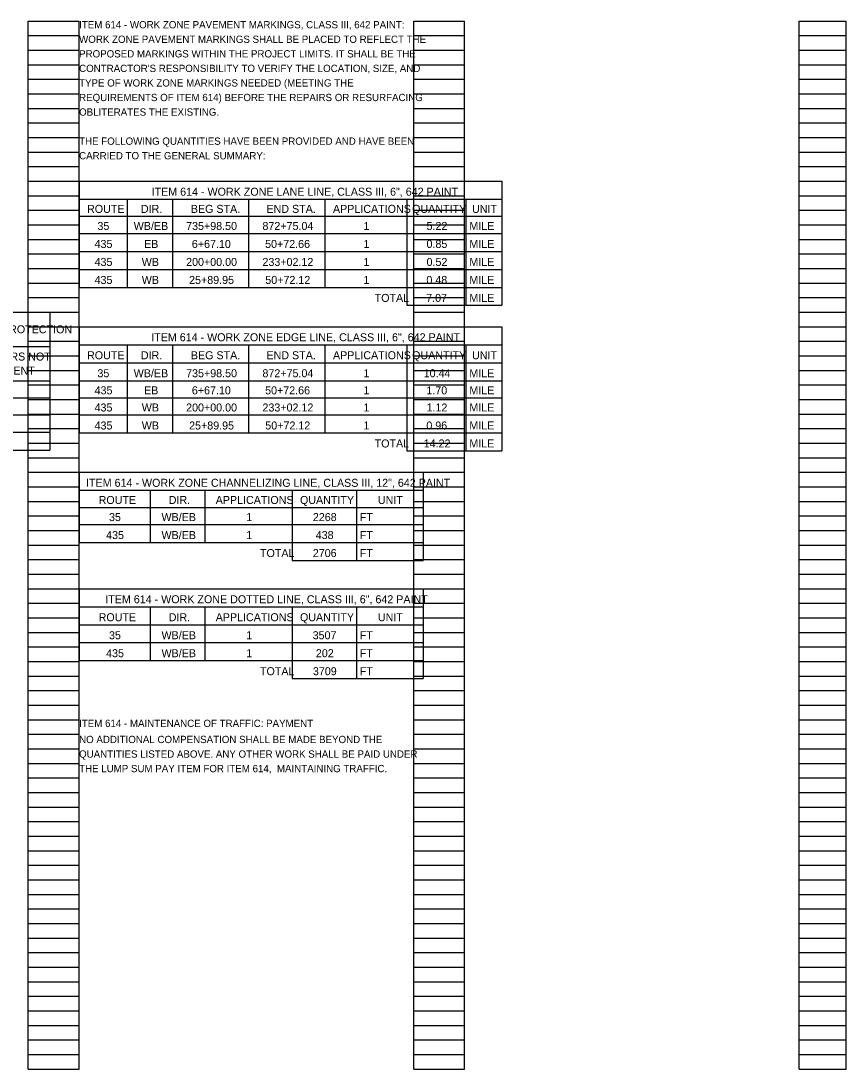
# Model space of a CAD drawing. Extents: x 51924.2 to 51956.2, y 31431.6 to 31530.7.
# Drawn here: x 51940.33 to 51956.21, y 31432.54 to 31452.7 of the extents above; entities that cross this region are included whole.
import ezdxf

# ---------------------------------------------------------------- set-up
doc = ezdxf.new("R2010")
doc.units = 0
doc.layers.add('SH_Data', color=7, linetype='Continuous')
doc.layers.add('SH_Text', color=7, linetype='Continuous')

msp = doc.modelspace()

# ---------------------------------------------------------------- linework, layer by layer
at = {"layer": 'SH_Data'}
for p, q in [((51940.468, 31432.54), (51940.468, 31452.7)), ((51940.468, 31452.7), (51941.448, 31452.7)), ((51941.448, 31432.54), (51941.448, 31452.7)), ((51947.888, 31432.54), (51947.888, 31452.7)), ((51947.888, 31452.7), (51948.868, 31452.7)), ((51948.868, 31432.54), (51948.868, 31452.7)), ((51955.308, 31432.54), (51955.308, 31452.7)), ((51955.308, 31452.7), (51956.208, 31452.7)), ((51956.208, 31432.54), (51956.208, 31452.7)), ((51940.468, 31452.42), (51941.448, 31452.42)), ((51947.888, 31452.42), (51948.868, 31452.42)), ((51955.308, 31452.42), (51956.208, 31452.42)), ((51940.468, 31452.14), (51941.448, 31452.14)), ((51947.888, 31452.14), (51948.868, 31452.14)), ((51955.308, 31452.14), (51956.208, 31452.14)), ((51940.468, 31451.86), (51941.448, 31451.86)), ((51947.888, 31451.86), (51948.868, 31451.86)), ((51955.308, 31451.86), (51956.208, 31451.86)), ((51940.468, 31451.58), (51941.448, 31451.58)), ((51947.888, 31451.58), (51948.868, 31451.58)), ((51955.308, 31451.58), (51956.208, 31451.58)), ((51940.468, 31451.3), (51941.448, 31451.3)), ((51947.888, 31451.3), (51948.868, 31451.3)), ((51955.308, 31451.3), (51956.208, 31451.3)), ((51940.468, 31451.02), (51941.448, 31451.02)), ((51947.888, 31451.02), (51948.868, 31451.02)), ((51955.308, 31451.02), (51956.208, 31451.02)), ((51940.468, 31450.74), (51941.448, 31450.74)), ((51947.888, 31450.74), (51948.868, 31450.74)), ((51955.308, 31450.74), (51956.208, 31450.74)), ((51940.468, 31450.46), (51941.448, 31450.46)), ((51947.888, 31450.46), (51948.868, 31450.46)), ((51955.308, 31450.46), (51956.208, 31450.46)), ((51940.468, 31450.18), (51941.448, 31450.18)), ((51947.888, 31450.18), (51948.868, 31450.18)), ((51955.308, 31450.18), (51956.208, 31450.18)), ((51940.468, 31449.9), (51941.448, 31449.9)), ((51947.888, 31449.9), (51948.868, 31449.9)), ((51955.308, 31449.9), (51956.208, 31449.9)), ((51940.468, 31449.62), (51941.448, 31449.62)), ((51947.888, 31449.62), (51948.868, 31449.62)), ((51955.308, 31449.62), (51956.208, 31449.62)), ((51940.468, 31449.34), (51941.448, 31449.34)), ((51947.888, 31449.34), (51948.868, 31449.34)), ((51955.308, 31449.34), (51956.208, 31449.34)), ((51940.468, 31449.06), (51941.448, 31449.06)), ((51947.888, 31449.06), (51948.868, 31449.06)), ((51955.308, 31449.06), (51956.208, 31449.06)), ((51940.468, 31448.78), (51941.448, 31448.78)), ((51947.888, 31448.78), (51948.868, 31448.78)), ((51955.308, 31448.78), (51956.208, 31448.78)), ((51940.468, 31448.5), (51941.448, 31448.5)), ((51947.888, 31448.5), (51948.868, 31448.5)), ((51955.308, 31448.5), (51956.208, 31448.5)), ((51940.468, 31448.22), (51941.448, 31448.22)), ((51947.888, 31448.22), (51948.868, 31448.22)), ((51955.308, 31448.22), (51956.208, 31448.22)), ((51940.468, 31447.94), (51941.448, 31447.94)), ((51947.888, 31447.94), (51948.868, 31447.94)), ((51955.308, 31447.94), (51956.208, 31447.94)), ((51940.468, 31447.66), (51941.448, 31447.66)), ((51947.888, 31447.66), (51948.868, 31447.66)), ((51955.308, 31447.66), (51956.208, 31447.66)), ((51940.468, 31447.38), (51941.448, 31447.38)), ((51947.888, 31447.38), (51948.868, 31447.38)), ((51955.308, 31447.38), (51956.208, 31447.38)), ((51940.468, 31447.1), (51941.448, 31447.1)), ((51947.888, 31447.1), (51948.868, 31447.1)), ((51955.308, 31447.1), (51956.208, 31447.1)), ((51940.468, 31446.82), (51941.448, 31446.82)), ((51947.888, 31446.82), (51948.868, 31446.82)), ((51955.308, 31446.82), (51956.208, 31446.82)), ((51940.468, 31446.54), (51941.448, 31446.54)), ((51947.888, 31446.54), (51948.868, 31446.54)), ((51955.308, 31446.54), (51956.208, 31446.54)), ((51940.468, 31446.26), (51941.448, 31446.26)), ((51947.888, 31446.26), (51948.868, 31446.26)), ((51955.308, 31446.26), (51956.208, 31446.26)), ((51940.468, 31445.98), (51941.448, 31445.98)), ((51947.888, 31445.98), (51948.868, 31445.98)), ((51955.308, 31445.98), (51956.208, 31445.98)), ((51940.468, 31445.7), (51941.448, 31445.7)), ((51947.888, 31445.7), (51948.868, 31445.7)), ((51955.308, 31445.7), (51956.208, 31445.7)), ((51940.468, 31445.42), (51941.448, 31445.42)), ((51947.888, 31445.42), (51948.868, 31445.42)), ((51955.308, 31445.42), (51956.208, 31445.42)), ((51940.468, 31445.14), (51941.448, 31445.14)), ((51947.888, 31445.14), (51948.868, 31445.14)), ((51955.308, 31445.14), (51956.208, 31445.14)), ((51940.468, 31444.86), (51941.448, 31444.86)), ((51947.888, 31444.86), (51948.868, 31444.86)), ((51955.308, 31444.86), (51956.208, 31444.86)), ((51940.468, 31444.58), (51941.448, 31444.58)), ((51947.888, 31444.58), (51948.868, 31444.58)), ((51955.308, 31444.58), (51956.208, 31444.58)), ((51940.468, 31444.3), (51941.448, 31444.3)), ((51947.888, 31444.3), (51948.868, 31444.3)), ((51955.308, 31444.3), (51956.208, 31444.3)), ((51940.468, 31444.02), (51941.448, 31444.02)), ((51947.888, 31444.02), (51948.868, 31444.02)), ((51955.308, 31444.02), (51956.208, 31444.02)), ((51940.468, 31443.74), (51941.448, 31443.74)), ((51947.888, 31443.74), (51948.868, 31443.74)), ((51955.308, 31443.74), (51956.208, 31443.74)), ((51940.468, 31443.46), (51941.448, 31443.46)), ((51947.888, 31443.46), (51948.868, 31443.46)), ((51955.308, 31443.46), (51956.208, 31443.46)), ((51940.468, 31443.18), (51941.448, 31443.18)), ((51947.888, 31443.18), (51948.868, 31443.18)), ((51955.308, 31443.18), (51956.208, 31443.18)), ((51940.468, 31442.9), (51941.448, 31442.9)), ((51947.888, 31442.9), (51948.868, 31442.9)), ((51955.308, 31442.9), (51956.208, 31442.9)), ((51940.468, 31442.62), (51941.448, 31442.62)), ((51947.888, 31442.62), (51948.868, 31442.62)), ((51955.308, 31442.62), (51956.208, 31442.62)), ((51940.468, 31442.34), (51941.448, 31442.34)), ((51947.888, 31442.34), (51948.868, 31442.34)), ((51955.308, 31442.34), (51956.208, 31442.34)), ((51940.468, 31442.06), (51941.448, 31442.06)), ((51947.888, 31442.06), (51948.868, 31442.06)), ((51955.308, 31442.06), (51956.208, 31442.06)), ((51940.468, 31441.78), (51941.448, 31441.78)), ((51947.888, 31441.78), (51948.868, 31441.78)), ((51955.308, 31441.78), (51956.208, 31441.78)), ((51940.468, 31441.5), (51941.448, 31441.5)), ((51947.888, 31441.5), (51948.868, 31441.5)), ((51955.308, 31441.5), (51956.208, 31441.5)), ((51940.468, 31441.22), (51941.448, 31441.22)), ((51947.888, 31441.22), (51948.868, 31441.22)), ((51955.308, 31441.22), (51956.208, 31441.22)), ((51940.468, 31440.94), (51941.448, 31440.94)), ((51947.888, 31440.94), (51948.868, 31440.94)), ((51955.308, 31440.94), (51956.208, 31440.94)), ((51940.468, 31440.66), (51941.448, 31440.66)), ((51947.888, 31440.66), (51948.868, 31440.66)), ((51955.308, 31440.66), (51956.208, 31440.66)), ((51940.468, 31440.38), (51941.448, 31440.38)), ((51947.888, 31440.38), (51948.868, 31440.38)), ((51955.308, 31440.38), (51956.208, 31440.38)), ((51940.468, 31440.1), (51941.448, 31440.1)), ((51947.888, 31440.1), (51948.868, 31440.1)), ((51955.308, 31440.1), (51956.208, 31440.1)), ((51940.468, 31439.82), (51941.448, 31439.82)), ((51947.888, 31439.82), (51948.868, 31439.82)), ((51955.308, 31439.82), (51956.208, 31439.82)), ((51940.468, 31439.54), (51941.448, 31439.54)), ((51947.888, 31439.54), (51948.868, 31439.54)), ((51955.308, 31439.54), (51956.208, 31439.54)), ((51940.468, 31439.26), (51941.448, 31439.26)), ((51947.888, 31439.26), (51948.868, 31439.26)), ((51955.308, 31439.26), (51956.208, 31439.26)), ((51940.468, 31438.98), (51941.448, 31438.98)), ((51947.888, 31438.98), (51948.868, 31438.98)), ((51955.308, 31438.98), (51956.208, 31438.98)), ((51940.468, 31438.7), (51941.448, 31438.7)), ((51947.888, 31438.7), (51948.868, 31438.7)), ((51955.308, 31438.7), (51956.208, 31438.7)), ((51940.468, 31438.42), (51941.448, 31438.42)), ((51947.888, 31438.42), (51948.868, 31438.42)), ((51955.308, 31438.42), (51956.208, 31438.42)), ((51940.468, 31438.14), (51941.448, 31438.14)), ((51947.888, 31438.14), (51948.868, 31438.14)), ((51955.308, 31438.14), (51956.208, 31438.14)), ((51940.468, 31437.86), (51941.448, 31437.86)), ((51947.888, 31437.86), (51948.868, 31437.86)), ((51955.308, 31437.86), (51956.208, 31437.86)), ((51940.468, 31437.58), (51941.448, 31437.58)), ((51947.888, 31437.58), (51948.868, 31437.58)), ((51955.308, 31437.58), (51956.208, 31437.58)), ((51940.468, 31437.3), (51941.448, 31437.3)), ((51947.888, 31437.3), (51948.868, 31437.3)), ((51955.308, 31437.3), (51956.208, 31437.3)), ((51940.468, 31437.02), (51941.448, 31437.02)), ((51947.888, 31437.02), (51948.868, 31437.02)), ((51955.308, 31437.02), (51956.208, 31437.02)), ((51940.468, 31436.74), (51941.448, 31436.74)), ((51947.888, 31436.74), (51948.868, 31436.74)), ((51955.308, 31436.74), (51956.208, 31436.74)), ((51940.468, 31436.46), (51941.448, 31436.46)), ((51947.888, 31436.46), (51948.868, 31436.46)), ((51955.308, 31436.46), (51956.208, 31436.46)), ((51940.468, 31436.18), (51941.448, 31436.18)), ((51947.888, 31436.18), (51948.868, 31436.18)), ((51955.308, 31436.18), (51956.208, 31436.18)), ((51940.468, 31435.9), (51941.448, 31435.9)), ((51947.888, 31435.9), (51948.868, 31435.9)), ((51955.308, 31435.9), (51956.208, 31435.9)), ((51940.468, 31435.62), (51941.448, 31435.62)), ((51947.888, 31435.62), (51948.868, 31435.62)), ((51955.308, 31435.62), (51956.208, 31435.62)), ((51940.468, 31435.34), (51941.448, 31435.34)), ((51947.888, 31435.34), (51948.868, 31435.34)), ((51955.308, 31435.34), (51956.208, 31435.34)), ((51940.468, 31435.06), (51941.448, 31435.06)), ((51947.888, 31435.06), (51948.868, 31435.06)), ((51955.308, 31435.06), (51956.208, 31435.06)), ((51940.468, 31434.78), (51941.448, 31434.78)), ((51947.888, 31434.78), (51948.868, 31434.78)), ((51955.308, 31434.78), (51956.208, 31434.78)), ((51940.468, 31434.5), (51941.448, 31434.5)), ((51947.888, 31434.5), (51948.868, 31434.5)), ((51955.308, 31434.5), (51956.208, 31434.5)), ((51940.468, 31434.22), (51941.448, 31434.22)), ((51947.888, 31434.22), (51948.868, 31434.22)), ((51955.308, 31434.22), (51956.208, 31434.22)), ((51940.468, 31433.94), (51941.448, 31433.94)), ((51947.888, 31433.94), (51948.868, 31433.94)), ((51955.308, 31433.94), (51956.208, 31433.94)), ((51940.468, 31433.66), (51941.448, 31433.66)), ((51947.888, 31433.66), (51948.868, 31433.66)), ((51955.308, 31433.66), (51956.208, 31433.66)), ((51940.468, 31433.38), (51941.448, 31433.38)), ((51947.888, 31433.38), (51948.868, 31433.38)), ((51955.308, 31433.38), (51956.208, 31433.38)), ((51940.468, 31433.1), (51941.448, 31433.1)), ((51947.888, 31433.1), (51948.868, 31433.1)), ((51955.308, 31433.1), (51956.208, 31433.1)), ((51940.468, 31432.82), (51941.448, 31432.82)), ((51947.888, 31432.82), (51948.868, 31432.82)), ((51955.308, 31432.82), (51956.208, 31432.82)), ((51940.468, 31432.54), (51941.448, 31432.54)), ((51947.888, 31432.54), (51948.868, 31432.54)), ((51955.308, 31432.54), (51956.208, 31432.54))]:
    msp.add_line(p, q, dxfattribs=at)
at = {"layer": 'SH_Text'}
for p, q in [((51941.448, 31449.62), (51949.585, 31449.62)), ((51941.448, 31449.62), (51941.448, 31447.577)), ((51949.585, 31449.62), (51949.585, 31447.232)), ((51941.448, 31449.274), (51949.585, 31449.274)), ((51942.371, 31449.274), (51942.371, 31447.577)), ((51943.244, 31449.274), (51943.244, 31447.577)), ((51944.71, 31449.274), (51944.71, 31447.577)), ((51946.176, 31449.274), (51946.176, 31447.577)), ((51947.757, 31449.274), (51947.757, 31447.577)), ((51948.893, 31449.274), (51948.893, 31447.232)), ((51941.448, 31448.944), (51949.585, 31448.944)), ((51941.448, 31448.615), (51949.585, 31448.615)), ((51941.448, 31448.269), (51949.585, 31448.269)), ((51941.448, 31447.923), (51949.585, 31447.923)), ((51941.448, 31447.577), (51949.585, 31447.577)), ((51947.757, 31447.577), (51947.757, 31447.232)), ((51947.757, 31447.232), (51949.585, 31447.232)), ((51933.048, 31447.1), (51940.888, 31447.1)), ((51940.888, 31447.1), (51940.888, 31444.448)), ((51941.448, 31446.82), (51949.585, 31446.82)), ((51941.448, 31446.82), (51941.448, 31444.777)), ((51949.585, 31446.82), (51949.585, 31444.432)), ((51933.048, 31446.441), (51940.888, 31446.441)), ((51941.448, 31446.474), (51949.585, 31446.474)), ((51942.371, 31446.474), (51942.371, 31444.777)), ((51943.244, 31446.474), (51943.244, 31444.777)), ((51944.71, 31446.474), (51944.71, 31444.777)), ((51946.176, 31446.474), (51946.176, 31444.777)), ((51947.757, 31446.474), (51947.757, 31444.777)), ((51948.893, 31446.474), (51948.893, 31444.432)), ((51941.448, 31446.128), (51949.585, 31446.128)), ((51933.048, 31445.782), (51940.888, 31445.782)), ((51941.448, 31445.782), (51949.585, 31445.782)), ((51933.048, 31445.453), (51940.888, 31445.453)), ((51941.448, 31445.453), (51949.585, 31445.453)), ((51933.048, 31445.123), (51940.888, 31445.123)), ((51941.448, 31445.123), (51949.585, 31445.123)), ((51933.048, 31444.794), (51940.888, 31444.794)), ((51941.448, 31444.777), (51949.585, 31444.777)), ((51947.757, 31444.777), (51947.757, 31444.432)), ((51933.048, 31444.448), (51940.888, 31444.448)), ((51947.757, 31444.432), (51949.585, 31444.432)), ((51941.448, 31444.02), (51948.07, 31444.02)), ((51941.448, 31444.02), (51941.448, 31442.669)), ((51948.07, 31444.02), (51948.07, 31442.323)), ((51941.448, 31443.674), (51948.07, 31443.674)), ((51942.816, 31443.674), (51942.816, 31442.669)), ((51943.87, 31443.674), (51943.87, 31442.669)), ((51945.55, 31443.674), (51945.55, 31442.669)), ((51946.785, 31443.674), (51946.785, 31442.323)), ((51941.448, 31443.344), (51948.07, 31443.344)), ((51941.448, 31443.015), (51948.07, 31443.015)), ((51941.448, 31442.669), (51948.07, 31442.669)), ((51945.55, 31442.669), (51945.55, 31442.323)), ((51945.55, 31442.323), (51948.07, 31442.323)), ((51941.448, 31441.78), (51948.07, 31441.78)), ((51941.448, 31441.78), (51941.448, 31440.396)), ((51948.07, 31441.78), (51948.07, 31440.05)), ((51941.448, 31441.434), (51948.07, 31441.434)), ((51942.816, 31441.434), (51942.816, 31440.396)), ((51943.87, 31441.434), (51943.87, 31440.396)), ((51945.55, 31441.434), (51945.55, 31440.396)), ((51946.785, 31441.434), (51946.785, 31440.05)), ((51941.448, 31441.088), (51948.07, 31441.088)), ((51941.448, 31440.742), (51948.07, 31440.742)), ((51941.448, 31440.396), (51948.07, 31440.396)), ((51945.55, 31440.396), (51945.55, 31440.05)), ((51945.55, 31440.05), (51948.07, 31440.05))]:
    msp.add_line(p, q, dxfattribs=at)

# ---------------------------------------------------------------- texts
for s, height, p in [('ITEM 614 - WORK ZONE PAVEMENT MARKINGS, CLASS III, 642 PAINT:', 0.14, (51941.448, 31452.56)), ('WORK ZONE PAVEMENT MARKINGS SHALL BE PLACED TO REFLECT THE ', 0.14, (51941.448, 31452.28)), ('PROPOSED MARKINGS WITHIN THE PROJECT LIMITS. IT SHALL BE THE ', 0.14, (51941.448, 31452)), ("CONTRACTOR'S RESPONSIBILITY TO VERIFY THE LOCATION, SIZE, AND ", 0.14, (51941.448, 31451.72)), ('TYPE OF WORK ZONE MARKINGS NEEDED (MEETING THE ', 0.14, (51941.448, 31451.44)), ('REQUIREMENTS OF ITEM 614) BEFORE THE REPAIRS OR RESURFACING ', 0.14, (51941.448, 31451.16)), ('OBLITERATES THE EXISTING.', 0.14, (51941.448, 31450.88)), ('THE FOLLOWING QUANTITIES HAVE BEEN PROVIDED AND HAVE BEEN ', 0.14, (51941.448, 31450.32)), ('CARRIED TO THE GENERAL SUMMARY:', 0.14, (51941.448, 31450.04)), ('ITEM 614 - WORK ZONE LANE LINE, CLASS III, 6", 642 PAINT', 0.154, (51942.844, 31449.34)), ('ROUTE', 0.154, (51941.601, 31449.01)), ('DIR.', 0.154, (51942.637, 31449.01)), ('BEG STA.', 0.154, (51943.599, 31449.01)), ('END STA.', 0.154, (51945.054, 31449.01)), ('APPLICATIONS', 0.154, (51946.334, 31449.01)), ('QUANTITY', 0.154, (51947.857, 31449.01)), ('UNIT', 0.154, (51949.01, 31449.01)), ('35', 0.154, (51941.801, 31448.681)), ('WB/EB', 0.154, (51942.499, 31448.681)), ('735+98.50', 0.154, (51943.508, 31448.681)), ('872+75.04', 0.154, (51944.977, 31448.681)), ('1', 0.154, (51946.921, 31448.681)), ('5.22', 0.154, (51948.135, 31448.681)), ('MILE', 0.154, (51948.959, 31448.681)), ('435', 0.154, (51941.746, 31448.335)), ('EB', 0.154, (51942.698, 31448.335)), ('6+67.10', 0.154, (51943.618, 31448.335)), ('50+72.66', 0.154, (51945.028, 31448.335)), ('1', 0.154, (51946.921, 31448.335)), ('0.85', 0.154, (51948.134, 31448.335)), ('MILE', 0.154, (51948.959, 31448.335)), ('435', 0.154, (51941.746, 31447.989)), ('WB', 0.154, (51942.654, 31447.989)), ('200+00.00', 0.154, (51943.508, 31447.989)), ('233+02.12', 0.154, (51944.977, 31447.989)), ('1', 0.154, (51946.921, 31447.989)), ('0.52', 0.154, (51948.135, 31447.989)), ('MILE', 0.154, (51948.959, 31447.989)), ('435', 0.154, (51941.746, 31447.643)), ('WB', 0.154, (51942.654, 31447.643)), ('25+89.95', 0.154, (51943.565, 31447.643)), ('50+72.12', 0.154, (51945.032, 31447.643)), ('1', 0.154, (51946.921, 31447.643)), ('0.48', 0.154, (51948.132, 31447.643)), ('MILE', 0.154, (51948.959, 31447.643)), ('TOTAL', 0.154, (51947.136, 31447.297)), ('7.07', 0.154, (51948.128, 31447.297)), ('MILE', 0.154, (51948.959, 31447.297)), ('WITHOUT POSITIVE PROTECTION', 0.154, (51937.939, 31446.693)), ('ITEM 614 - WORK ZONE EDGE LINE, CLASS III, 6", 642 PAINT', 0.154, (51942.836, 31446.54)), ('WORKERS NOT ', 0.154, (51939.347, 31446.169)), ('ROUTE', 0.154, (51941.601, 31446.194)), ('DIR.', 0.154, (51942.637, 31446.194)), ('BEG STA.', 0.154, (51943.599, 31446.194)), ('END STA.', 0.154, (51945.054, 31446.194)), ('APPLICATIONS', 0.154, (51946.334, 31446.194)), ('QUANTITY', 0.154, (51947.857, 31446.194)), ('UNIT', 0.154, (51949.01, 31446.194)), ('PRESENT', 0.154, (51939.623, 31445.9)), ('35', 0.154, (51941.801, 31445.848)), ('WB/EB', 0.154, (51942.499, 31445.848)), ('735+98.50', 0.154, (51943.508, 31445.848)), ('872+75.04', 0.154, (51944.977, 31445.848)), ('1', 0.154, (51946.921, 31445.848)), ('10.44', 0.154, (51948.08, 31445.848)), ('MILE', 0.154, (51948.959, 31445.848)), ('435', 0.154, (51941.746, 31445.519)), ('EB', 0.154, (51942.698, 31445.519)), ('6+67.10', 0.154, (51943.618, 31445.519)), ('50+72.66', 0.154, (51945.028, 31445.519)), ('1', 0.154, (51946.921, 31445.519)), ('1.70', 0.154, (51948.132, 31445.519)), ('MILE', 0.154, (51948.959, 31445.519)), ('435', 0.154, (51941.746, 31445.189)), ('WB', 0.154, (51942.654, 31445.189)), ('200+00.00', 0.154, (51943.508, 31445.189)), ('233+02.12', 0.154, (51944.977, 31445.189)), ('1', 0.154, (51946.921, 31445.189)), ('1.12', 0.154, (51948.135, 31445.189)), ('MILE', 0.154, (51948.959, 31445.189)), ('435', 0.154, (51941.746, 31444.843)), ('WB', 0.154, (51942.654, 31444.843)), ('25+89.95', 0.154, (51943.565, 31444.843)), ('50+72.12', 0.154, (51945.032, 31444.843)), ('1', 0.154, (51946.921, 31444.843)), ('0.96', 0.154, (51948.131, 31444.843)), ('MILE', 0.154, (51948.959, 31444.843)), ('TOTAL', 0.154, (51947.136, 31444.497)), ('14.22', 0.154, (51948.08, 31444.497)), ('MILE', 0.154, (51948.959, 31444.497)), ('ITEM 614 - WORK ZONE CHANNELIZING LINE, CLASS III, 12", 642 PAINT', 0.154, (51941.582, 31443.74)), ('ROUTE', 0.154, (51941.824, 31443.41)), ('DIR.', 0.154, (51943.173, 31443.41)), ('APPLICATIONS', 0.154, (51944.077, 31443.41)), ('QUANTITY', 0.154, (51945.699, 31443.41)), ('UNIT', 0.154, (51947.199, 31443.41)), ('35', 0.154, (51942.024, 31443.081)), ('WB/EB', 0.154, (51943.034, 31443.081)), ('1', 0.154, (51944.664, 31443.081)), ('2268', 0.154, (51945.947, 31443.081)), ('FT', 0.154, (51946.851, 31443.081)), ('435', 0.154, (51941.968, 31442.735)), ('WB/EB', 0.154, (51943.034, 31442.735)), ('1', 0.154, (51944.664, 31442.735)), ('438', 0.154, (51946.002, 31442.735)), ('FT', 0.154, (51946.851, 31442.735)), ('TOTAL', 0.154, (51944.929, 31442.389)), ('2706', 0.154, (51945.946, 31442.389)), ('FT', 0.154, (51946.851, 31442.389)), ('ITEM 614 - WORK ZONE DOTTED LINE, CLASS III, 6", 642 PAINT', 0.154, (51941.952, 31441.5)), ('ROUTE', 0.154, (51941.824, 31441.154)), ('DIR.', 0.154, (51943.173, 31441.154)), ('APPLICATIONS', 0.154, (51944.077, 31441.154)), ('QUANTITY', 0.154, (51945.699, 31441.154)), ('UNIT', 0.154, (51947.199, 31441.154)), ('35', 0.154, (51942.024, 31440.808)), ('WB/EB', 0.154, (51943.034, 31440.808)), ('1', 0.154, (51944.664, 31440.808)), ('3507', 0.154, (51945.943, 31440.808)), ('FT', 0.154, (51946.851, 31440.808)), ('435', 0.154, (51941.968, 31440.462)), ('WB/EB', 0.154, (51943.034, 31440.462)), ('1', 0.154, (51944.664, 31440.462)), ('202', 0.154, (51946.005, 31440.462)), ('FT', 0.154, (51946.851, 31440.462)), ('TOTAL', 0.154, (51944.929, 31440.116)), ('3709', 0.154, (51945.948, 31440.116)), ('FT', 0.154, (51946.851, 31440.116)), ('ITEM 614 - MAINTENANCE OF TRAFFIC: PAYMENT', 0.14, (51941.448, 31439.12)), ('NO ADDITIONAL COMPENSATION SHALL BE MADE BEYOND THE ', 0.14, (51941.448, 31438.81)), ('QUANTITIES LISTED ABOVE. ANY OTHER WORK SHALL BE PAID UNDER ', 0.14, (51941.448, 31438.53)), ('THE LUMP SUM PAY ITEM FOR ITEM 614,  MAINTAINING TRAFFIC.', 0.14, (51941.448, 31438.25))]:
    msp.add_text(s, height=height, dxfattribs=at).set_placement(p)

doc.saveas('drawing.dxf')
